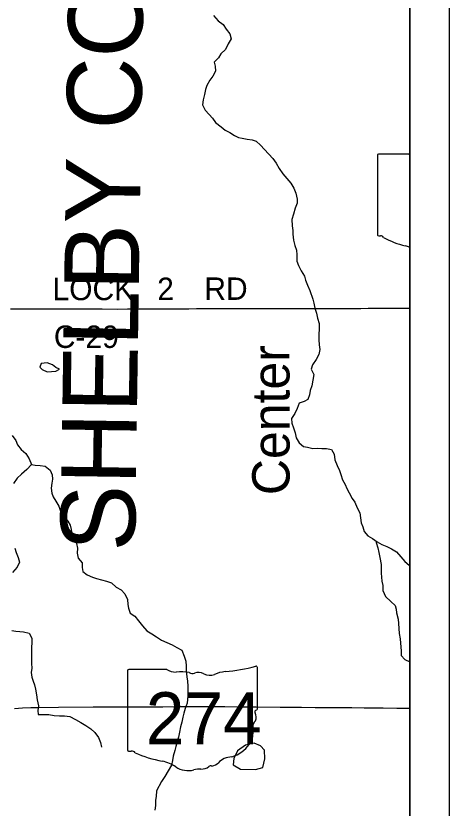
# Model space of a CAD drawing. Extents: x 0 to 34, y 0 to 22.
# Drawn here: x 7.901 to 9, y 17.185 to 19.194 of the extents above; entities that cross this region are included whole.
import ezdxf

# ---------------------------------------------------------------- set-up
doc = ezdxf.new("R2010")
doc.units = 0
for name, color, linetype in [('GM_X_Corporation', 7, 'Continuous'), ('GM_X_County_Road', 7, 'Continuous'), ('GM_X_County_Road_Text', 7, 'Continuous'), ('GM_X_County_Text', 7, 'Continuous'), ('GM_X_Minor_Lake', 7, 'Continuous'), ('GM_X_Minor_River', 7, 'Continuous'), ('GM_X_Minor_River_Text', 7, 'Continuous'), ('GM_X_State_Location', 7, 'Continuous'), ('GM_X_State_Route', 7, 'Continuous'), ('GM_X_State_Shield', 7, 'Continuous'), ('SH_Data', 7, 'Continuous')]:
    doc.layers.add(name, color=color, linetype=linetype)

msp = doc.modelspace()

# ---------------------------------------------------------------- linework, layer by layer
at = {"layer": 'GM_X_Corporation'}
for points in [[(8.9, 14.1), (8.9, 20.4201)], [(8.9, 16.4207), (8.9, 20.4201)]]:
    msp.add_lwpolyline(points, dxfattribs=at)
at = {"layer": 'GM_X_County_Road'}
msp.add_lwpolyline([(7.8876, 18.4508), (7.9112, 18.4508), (7.9554, 18.4508), (7.9883, 18.4509), (8.0343, 18.4509), (8.0573, 18.4509), (8.0772, 18.4508), (8.0983, 18.4508), (8.12, 18.4509), (8.1598, 18.4506), (8.1841, 18.4507), (8.2431, 18.4509), (8.2586, 18.4509), (8.2655, 18.451), (8.2847, 18.4511), (8.3146, 18.4512), (8.34, 18.4514), (8.3593, 18.4515), (8.3767, 18.4517), (8.3885, 18.4517), (8.4009, 18.4517), (8.4295, 18.4516), (8.4513, 18.4517), (8.4861, 18.4518), (8.4948, 18.4518), (8.5234, 18.4519), (8.5383, 18.4519), (8.5488, 18.4519), (8.5619, 18.452), (8.6091, 18.4519), (8.6621, 18.4518), (8.6731, 18.4518), (8.7048, 18.4517), (8.7129, 18.4518), (8.7359, 18.4521), (8.7607, 18.4522), (8.7763, 18.4522), (8.7949, 18.4525), (8.8017, 18.4525), (8.8185, 18.4525), (8.8253, 18.4524), (8.8427, 18.4525), (8.8546, 18.4526), (8.862, 18.4527), (8.8688, 18.4528), (8.8819, 18.4529), (8.8906, 18.4529), (8.9, 18.4529)], dxfattribs=at)
at = {"layer": 'GM_X_Minor_Lake'}
for points in [[(7.9805, 18.314), (7.9654, 18.3122), (7.9618, 18.3032), (7.9682, 18.297), (7.9807, 18.2915)], [(7.9807, 18.2915), (8.0029, 18.2929), (8.0117, 18.2984), (8.0023, 18.302), (7.994, 18.3094), (7.9805, 18.314)], [(8.4832, 17.3446), (8.4635, 17.3305), (8.454, 17.3109), (8.4526, 17.2949), (8.4711, 17.2835), (8.5086, 17.2834)], [(8.5086, 17.2834), (8.5276, 17.2878), (8.5326, 17.3101), (8.5319, 17.3322), (8.5218, 17.3431), (8.5058, 17.3495), (8.4832, 17.3446)]]:
    msp.add_lwpolyline(points, dxfattribs=at)
at = {"layer": 'GM_X_Minor_River'}
for points in [[(8.4024, 19.1944), (8.414, 19.1813), (8.4268, 19.1719), (8.4342, 19.16), (8.4439, 19.1484), (8.4475, 19.1358), (8.4393, 19.1226), (8.4325, 19.1083), (8.4209, 19.0979), (8.4153, 19.0877), (8.4044, 19.0761), (8.4065, 19.0662), (8.4074, 19.054), (8.4011, 19.0412), (8.3929, 19.0311), (8.3858, 19.0171), (8.3821, 19.0073), (8.3796, 18.9948), (8.3759, 18.9812), (8.3745, 18.9683), (8.3815, 18.9548), (8.3916, 18.944), (8.3995, 18.9343), (8.4077, 18.9239), (8.4216, 18.9126), (8.4321, 18.9041), (8.4435, 18.8981), (8.4559, 18.8903), (8.4657, 18.8855), (8.4753, 18.8838), (8.4878, 18.8813), (8.5007, 18.8792), (8.5102, 18.8759), (8.5219, 18.8662), (8.532, 18.855), (8.5529, 18.8325), (8.5615, 18.8202), (8.5692, 18.8067), (8.5781, 18.7933), (8.5886, 18.7816), (8.5987, 18.7697), (8.6061, 18.757), (8.6108, 18.7443), (8.6144, 18.7294), (8.6142, 18.7192), (8.6093, 18.7059), (8.6056, 18.6912), (8.6012, 18.6772), (8.602, 18.6616), (8.6037, 18.6497), (8.6039, 18.6402), (8.6056, 18.6254), (8.6084, 18.612), (8.6127, 18.6001), (8.614, 18.5879), (8.6137, 18.5723), (8.6177, 18.5612), (8.6247, 18.5474), (8.6329, 18.5339), (8.6361, 18.5236), (8.6405, 18.5109), (8.6463, 18.4975), (8.6543, 18.4753), (8.6568, 18.4657), (8.6596, 18.4531), (8.6632, 18.4401), (8.6664, 18.4271), (8.67, 18.4141), (8.6701, 18.4), (8.6698, 18.3863), (8.6692, 18.3727), (8.6705, 18.3597)], [(8.6705, 18.3597), (8.6722, 18.3482), (8.6696, 18.335), (8.6626, 18.3226), (8.6531, 18.3094), (8.6503, 18.2977), (8.6569, 18.2846), (8.6543, 18.2698), (8.6514, 18.2562), (8.6474, 18.2437), (8.646, 18.2331), (8.642, 18.221), (8.632, 18.2158), (8.6197, 18.2115), (8.6145, 18.1986), (8.6085, 18.1854), (8.5999, 18.1734), (8.6008, 18.1612), (8.6055, 18.1493), (8.6091, 18.1363), (8.6123, 18.1241), (8.6197, 18.1114), (8.6303, 18.1024), (8.6405, 18.1), (8.6542, 18.097), (8.6668, 18.0976), (8.6767, 18.097), (8.6893, 18.0971), (8.7019, 18.0942), (8.7085, 18.0827), (8.7102, 18.0678), (8.7156, 18.054), (8.7219, 18.0409), (8.7255, 18.0306), (8.7295, 18.0176), (8.7365, 18.0053), (8.7409, 17.9953), (8.7468, 17.9845), (8.7542, 17.9703), (8.7605, 17.9607), (8.7667, 17.9461), (8.7737, 17.9334), (8.775, 17.9208), (8.7771, 17.9082), (8.7807, 17.8982), (8.7847, 17.8867), (8.794, 17.8752), (8.8057, 17.8688), (8.8178, 17.8606), (8.8295, 17.8535), (8.842, 17.8487), (8.8541, 17.8428), (8.8666, 17.8346), (8.8778, 17.8226), (8.8875, 17.8102), (8.8984, 17.8012), (8.9, 17.8001)], [(7.8922, 18.1298), (7.9012, 18.1175), (7.9055, 18.106), (7.9149, 18.0947), (7.9265, 18.0839), (7.935, 18.0704), (7.9405, 18.0566), (7.9288, 18.0438), (7.9152, 18.0315), (7.9044, 18.0215), (7.8953, 18.0083)], [(7.9405, 18.0566), (7.95, 18.0549), (7.963, 18.0542), (7.9755, 18.0525), (7.988, 18.0423), (7.9931, 18.0304), (7.994, 18.019), (7.9927, 18.0087), (7.9909, 17.9966), (7.9926, 17.984), (7.9959, 17.974), (8.0025, 17.9636), (8.0103, 17.9505), (8.0147, 17.9379), (8.0221, 17.9256), (8.0329, 17.9124), (8.0388, 17.9024), (8.0413, 17.8913), (8.0434, 17.8806), (8.0493, 17.8676), (8.0548, 17.8557), (8.0576, 17.8438), (8.0566, 17.8313), (8.0595, 17.819), (8.0692, 17.8067), (8.0693, 17.7949), (8.0707, 17.7853), (8.0823, 17.7767), (8.0956, 17.7711), (8.1055, 17.7675), (8.1184, 17.7638), (8.1313, 17.7606), (8.1438, 17.7561), (8.1558, 17.7452), (8.1683, 17.7385), (8.1776, 17.7281), (8.1843, 17.7139), (8.1848, 17.7017), (8.1865, 17.6921), (8.1909, 17.6791), (8.203, 17.672), (8.2123, 17.66), (8.2224, 17.6473), (8.2336, 17.6349), (8.2456, 17.627), (8.2577, 17.6192), (8.2702, 17.6109), (8.2842, 17.605), (8.2978, 17.5994), (8.3095, 17.5923), (8.322, 17.5852), (8.3282, 17.5706), (8.3318, 17.558), (8.3327, 17.545), (8.3328, 17.5321), (8.3349, 17.518), (8.3366, 17.5073), (8.3371, 17.4943), (8.3369, 17.481), (8.3375, 17.4707), (8.3361, 17.4604), (8.3352, 17.4509), (8.3307, 17.4373), (8.3271, 17.426), (8.3242, 17.4154), (8.3221, 17.4032), (8.3188, 17.3911), (8.3163, 17.3774), (8.3134, 17.3649), (8.3105, 17.3539), (8.3065, 17.3411), (8.304, 17.3312), (8.2999, 17.3168), (8.2986, 17.3058), (8.2957, 17.2937), (8.2874, 17.2793), (8.2788, 17.2654), (8.2701, 17.2526), (8.2575, 17.2285), (8.2569, 17.2144), (8.2555, 17.2049), (8.2549, 17.1916), (8.2536, 17.1798)], [(8.8154, 17.8622), (8.8151, 17.8588), (8.819, 17.845), (8.8215, 17.8335), (8.8243, 17.8205), (8.8274, 17.803), (8.8276, 17.7934), (8.8278, 17.7809), (8.8288, 17.7706), (8.8293, 17.7607), (8.8314, 17.7496), (8.8319, 17.7366), (8.8389, 17.722), (8.8517, 17.7092), (8.8629, 17.6991), (8.8654, 17.6896), (8.8668, 17.68), (8.8703, 17.664), (8.8716, 17.6533), (8.8722, 17.6407), (8.8735, 17.6277), (8.8755, 17.614), (8.8768, 17.6037), (8.8778, 17.5938), (8.8784, 17.5831), (8.8786, 17.5724), (8.8872, 17.562), (8.9, 17.556)], [(7.8985, 17.8446), (7.9017, 17.8335), (7.9072, 17.8208), (7.91, 17.8085), (7.9045, 17.7957), (7.8924, 17.7826)], [(7.8912, 17.6353), (7.9011, 17.6339), (7.911, 17.633), (7.9209, 17.6317), (7.9346, 17.6284), (7.9417, 17.616), (7.9419, 17.6061), (7.9412, 17.5913), (7.941, 17.5783), (7.9411, 17.5646), (7.9409, 17.5517), (7.9414, 17.5399), (7.9401, 17.5292), (7.9414, 17.517), (7.945, 17.5074), (7.9483, 17.4979), (7.9508, 17.4864), (7.9539, 17.4726), (7.9552, 17.4593), (7.9588, 17.4447), (7.9567, 17.4326), (7.9576, 17.4227), (7.9717, 17.4228), (7.9847, 17.4225), (7.9984, 17.4196), (8.0117, 17.4193), (8.0247, 17.4187), (8.0377, 17.4173), (8.052, 17.4098), (8.0656, 17.402), (8.0785, 17.3945), (8.0909, 17.3859), (8.1014, 17.3769), (8.1111, 17.3638), (8.1155, 17.3511), (8.1187, 17.3396)]]:
    msp.add_lwpolyline(points, dxfattribs=at)
at = {"layer": 'GM_X_State_Route'}
msp.add_lwpolyline([(7.8978, 17.438), (7.9183, 17.4393), (7.9394, 17.4402), (7.9586, 17.4406), (8.0089, 17.4413), (8.0971, 17.4417), (8.1611, 17.4418), (8.2084, 17.4421), (8.2338, 17.4421), (8.2742, 17.4422), (8.3084, 17.4424), (8.368, 17.4425), (8.4078, 17.4424), (8.4308, 17.4424), (8.4656, 17.4421), (8.5103, 17.4422), (8.5718, 17.4413), (8.6035, 17.4411), (8.6252, 17.4409), (8.66, 17.4404), (8.7097, 17.4402), (8.7532, 17.4398), (8.7843, 17.4396), (8.8328, 17.4391), (8.8676, 17.4389), (8.9, 17.4387)], dxfattribs=at)
at = {"layer": 'GM_X_State_Shield'}
for p, q in [((8.818, 18.8397), (8.818, 18.6396)), ((8.8978, 18.8432), (8.8205, 18.8432)), ((8.9, 18.6069), (8.9, 18.8416)), ((8.5137, 17.4368), (8.5137, 17.5415)), ((8.1841, 17.5331), (8.1841, 17.3329)), ((8.2839, 17.5365), (8.1873, 17.5365)), ((8.5137, 17.4368), (8.5137, 17.4368))]:
    msp.add_line(p, q, dxfattribs=at)
for centre, radius, start, end in [((8.821, 18.8402), 0.00305, 98.978, 188.5967), ((8.9162, 18.8664), 0.0296, 231.6404, 236.8722), ((8.821, 18.6392), 0.00308, 171.4911, 258.3065), ((8.8215, 18.6596), 0.0235, 267.339, 280.6039), ((8.8263, 18.6281), 0.00848, 29.7484, 93.2717), ((8.9334, 18.8079), 0.2019, 240.4129, 257.1985), ((8.8732, 18.5497), 0.0632, 64.8773, 75.836)]:
    msp.add_arc(centre, radius, start, end, dxfattribs=at)
for centre, major_axis, start_param, end_param in [((8.3963, 17.8093), (0.3495, 0), 4.814394, 5.042369), ((8.51, 17.5419), (0.00367, 0), 6.141152, 7.989035), ((8.1879, 17.5335), (0.00382, 0), 1.712693, 3.28349), ((8.3069, 17.5597), (0.037, 0), 4.042523, 4.731795), ((8.3191, 17.4242), (0.133, 0), 1.404758, 1.657858), ((8.3493, 17.5345), (0.0107, 0), 3.836095, 5.185415), ((8.365, 17.5114), (0.0222, 0), 0.950623, 2.079405), ((8.3937, 17.5431), (0.0267, 0), 4.081561, 5.145723), ((8.4409, 17.4754), (0.0703, 0), 1.699011, 2.107814), ((8.5128, 17.4291), (0.00568, 0), 1.883978, 3.671073), ((8.4767, 17.4159), (0.0341, 0), 5.934695, 6.695948), ((8.5098, 17.4364), (0.00393, 0), 5.05454, 6.418171), ((8.5268, 17.393), (0.0248, 0), 2.387724, 3.262537), ((8.4159, 17.3797), (0.0874, 0), 5.101752, 6.440018), ((8.1879, 17.3325), (0.00385, 0), 3.00124, 4.508301), ((8.1885, 17.353), (0.0294, 0), 4.665946, 4.897461), ((8.1945, 17.3214), (0.0106, 0), 0.519207, 1.627899), ((8.3283, 17.5012), (0.2524, 0), 4.195997, 4.488961), ((8.2531, 17.243), (0.079, 0), 0.823519, 1.323587), ((8.3921, 17.3135), (0.0282, 0), 4.937069, 5.64225), ((8.4527, 17.2768), (0.0479, 0), 1.647645, 2.488434), ((8.3385, 17.3204), (0.0501, 0), 4.026481, 4.996735), ((8.3675, 17.2512), (0.0412, 0), 1.495662, 1.94098), ((8.3711, 17.3054), (0.0267, 0), 4.691044, 5.507374), ((8.3953, 17.286), (0.00752, 0), 1.147584, 2.315152)]:
    msp.add_ellipse(centre, major_axis=major_axis, ratio=0.8, start_param=start_param, end_param=end_param, dxfattribs=at)
at = {"layer": 'SH_Data'}
for p, q in [((9, 21), (9, 14)), ((8.9, 20.9), (8.9, 14.1)), ((8.9, 20.9), (8.9, 14.1))]:
    msp.add_line(p, q, dxfattribs=at)

# ---------------------------------------------------------------- texts
at = {"layer": 'GM_X_County_Road_Text'}
for s, height, rotation, p in [('LOCK', 0.05682, 0, (7.9942, 18.473)), ('2', 0.0568, 1.1098, (8.2603, 18.473)), ('RD', 0.05682, 0, (8.3792, 18.4738)), ('C-29', 0.05682, 0, (7.9975, 18.3519))]:
    msp.add_text(s, height=height, rotation=rotation, dxfattribs=at).set_placement(p)
at = {"layer": 'GM_X_County_Text'}
msp.add_text('SHELBY COUNTY', height=0.189394, rotation=89.1576, dxfattribs=at).set_placement((8.2031, 17.8348))
at = {"layer": 'GM_X_Minor_River_Text'}
msp.add_text('Center', height=0.09476, rotation=90.0581, dxfattribs=at).set_placement((8.5954, 17.9787))
at = {"layer": 'GM_X_State_Location'}
for s, p in [('29', (8.8992, 18.7126)), ('274', (8.2783, 17.4059))]:
    msp.add_text(s, height=0.000189, rotation=0, dxfattribs=at).set_placement(p)
for s in ['s', 'r']:
    msp.add_text(s, height=0.000189, dxfattribs=at).set_placement((8.3452, 17.4197))
at = {"layer": 'GM_X_State_Shield'}
msp.add_text('274', height=0.13184, dxfattribs=at).set_placement((8.2306, 17.3471))

doc.saveas('drawing.dxf')
